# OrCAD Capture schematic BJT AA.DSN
size A
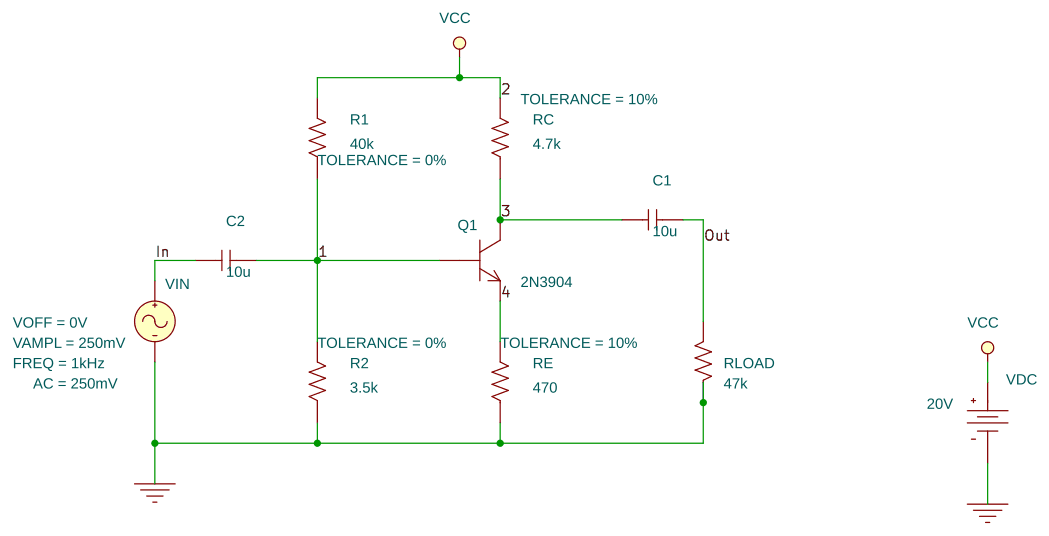
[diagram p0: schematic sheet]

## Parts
C1  10u  [RAD/CK05]
C2  10u  [RAD/CK05]
Q1  2N3904  [TO92]
R1  40k  [AX/RC05]
R2  3.5k  [AX/RC05]
RC  4.7k  [AX/RC05]
RE  470  [AX/RC05]
RLOAD  47k  [AX/RC05]
VDC  VDC
VIN  VSIN

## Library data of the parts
C1 C2 = C
Q1 = 2N3904
R1 R2 RLOAD = R: TOLERANCE: 0%
RC RE = R: TOLERANCE: 10%
VDC = VDC: DC: 20V
VIN = VSIN: AC: 250mV; FREQ: 1kHz; VAMPL: 250mV; VOFF: 0V

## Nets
VCC: R1.2 RC.2 VDC.0(+)
0: R2.1 RE.1 RLOAD.1 VDC.1(-) VIN.2(-)
1: C2.2 Q1.2(B) R1.1 R2.2
3: C1.1 Q1.3(C) RC.1
4: Q1.1(E) RE.2
In: C2.1 VIN.1(+)
Out: C1.2 RLOAD.2
